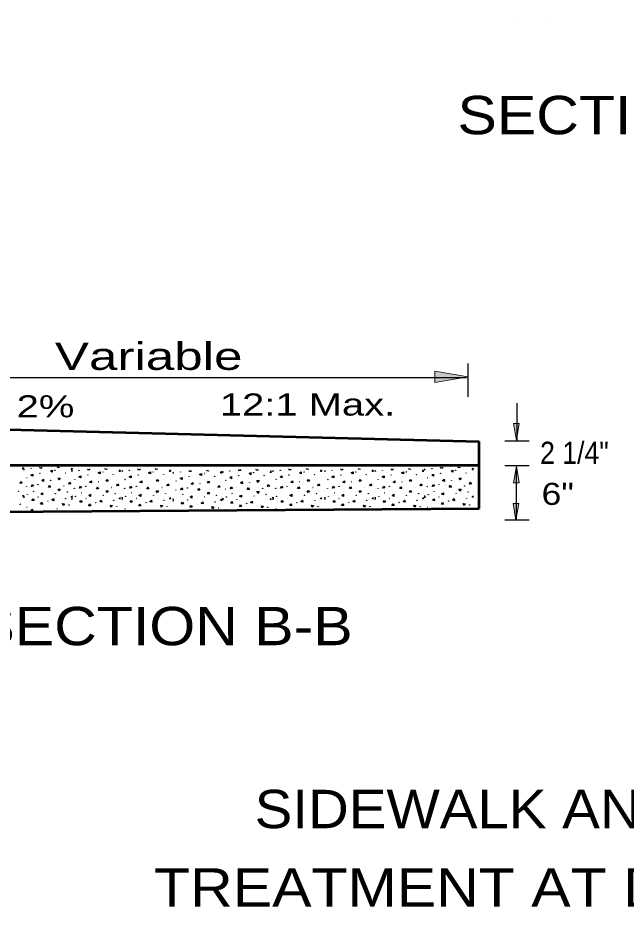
# Model space of a CAD drawing. Extents: x 75.6 to 110.9, y 28 to 50.
# Drawn here: x 94.747 to 98.089, y 33.984 to 38.874 of the extents above; entities that cross this region are included whole.
import ezdxf
from ezdxf.enums import TextEntityAlignment as Align

# ---------------------------------------------------------------- set-up
doc = ezdxf.new("R2010")
doc.units = 0
doc.header["$LTSCALE"] = 0.06
for name, color, linetype, lineweight in [('1', 7, 'Continuous', 25), ('3', 7, 'Continuous', 13), ('4', 7, 'Continuous', 53)]:
    doc.layers.add(name, color=color, linetype=linetype, lineweight=lineweight)

msp = doc.modelspace()

# ---------------------------------------------------------------- hatches: boundary and pattern name
at = {"layer": '3'}
for points in [[(97.03675, 36.9305), (97.03675, 36.86892), (97.22133, 36.89975), (97.22133, 36.89975)], [(97.50075, 36.644), (97.47, 36.644), (97.48542, 36.55167), (97.48542, 36.55167)], [(97.50075, 36.31617), (97.47, 36.31617), (97.48542, 36.4085), (97.48542, 36.4085)], [(97.49858, 36.20383), (97.46775, 36.20383), (97.48317, 36.1115), (97.48317, 36.1115)]]:
    msp.add_hatch(color=256, dxfattribs=at).paths.add_polyline_path(points)

# ---------------------------------------------------------------- linework, layer by layer
at = {"layer": '1', "lineweight": 53}
for p, q in [((97.28183, 36.17567), (97.28183, 36.54392)), ((93.93933, 36.41383), (97.27217, 36.41383)), ((93.94317, 36.15208), (97.28183, 36.17567))]:
    msp.add_line(p, q, dxfattribs=at)
at = {"layer": '1'}
for p, q in [((94.77275, 36.39208), (94.77858, 36.40208)), ((94.7805, 36.39208), (94.77275, 36.39208)), ((94.778, 36.3945), (94.782, 36.38767)), ((94.782, 36.38767), (94.778, 36.38767)), ((94.77858, 36.40208), (94.7805, 36.39883)), ((94.86742, 36.3975), (94.87075, 36.40325)), ((94.87908, 36.3975), (94.86742, 36.3975)), ((94.87575, 36.40325), (94.87908, 36.3975)), ((94.96258, 36.40267), (94.96333, 36.40325)), ((94.97358, 36.39867), (94.96258, 36.40267)), ((94.97275, 36.40325), (94.97358, 36.39867)), ((95.04033, 36.38767), (95.04608, 36.39767)), ((95.048, 36.38767), (95.04033, 36.38767)), ((95.04117, 36.38567), (95.04508, 36.37883)), ((95.04608, 36.39767), (95.048, 36.3945)), ((95.13058, 36.38867), (95.134, 36.3945)), ((95.14225, 36.38867), (95.13058, 36.38867)), ((95.13892, 36.3945), (95.14225, 36.38867)), ((95.22575, 36.39383), (95.22642, 36.3945)), ((95.23667, 36.38983), (95.22575, 36.39383)), ((95.23592, 36.3945), (95.23667, 36.38983)), ((95.30342, 36.37883), (95.30925, 36.38883)), ((95.30925, 36.38883), (95.31117, 36.38567)), ((95.31733, 36.38567), (95.32133, 36.37883)), ((95.40683, 36.38867), (95.41017, 36.3945)), ((95.4185, 36.38867), (95.40683, 36.38867)), ((95.41517, 36.3945), (95.4185, 36.38867)), ((95.502, 36.39383), (95.50267, 36.3945)), ((95.513, 36.38983), (95.502, 36.39383)), ((95.51217, 36.3945), (95.513, 36.38983)), ((95.57967, 36.37883), (95.5855, 36.38883)), ((95.5855, 36.38883), (95.58733, 36.38567)), ((95.68758, 36.37992), (95.69092, 36.38567)), ((95.69917, 36.37992), (95.68758, 36.37992)), ((95.69583, 36.38567), (95.69917, 36.37992)), ((95.78267, 36.38517), (95.78333, 36.38567)), ((95.79367, 36.38117), (95.78267, 36.38517)), ((95.79283, 36.38567), (95.79367, 36.38117)), ((95.86033, 36.37008), (95.86617, 36.38017)), ((95.86617, 36.38017), (95.86808, 36.37683)), ((95.87, 36.38125), (95.874, 36.3745)), ((95.95942, 36.38433), (95.96275, 36.39008)), ((95.97108, 36.38433), (95.95942, 36.38433)), ((95.96775, 36.39008), (95.97108, 36.38433)), ((96.05458, 36.3895), (96.05533, 36.39008)), ((96.06558, 36.3855), (96.05458, 36.3895)), ((96.06475, 36.39008), (96.06558, 36.3855)), ((96.13233, 36.3745), (96.13808, 36.3845)), ((96.13808, 36.3845), (96.14, 36.38125)), ((96.14633, 36.38567), (96.15025, 36.37883)), ((96.23575, 36.38875), (96.23908, 36.3945)), ((96.24733, 36.38875), (96.23575, 36.38875)), ((96.244, 36.3945), (96.24733, 36.38875)), ((96.33092, 36.39392), (96.33158, 36.3945)), ((96.34183, 36.38992), (96.33092, 36.39392)), ((96.341, 36.3945), (96.34183, 36.38992)), ((96.40858, 36.37883), (96.41433, 36.38892)), ((96.41433, 36.38892), (96.41633, 36.38567)), ((96.43133, 36.38567), (96.43533, 36.37883)), ((96.52075, 36.38875), (96.52417, 36.3945)), ((96.53242, 36.38875), (96.52075, 36.38875)), ((96.52908, 36.3945), (96.53242, 36.38875)), ((96.616, 36.39392), (96.61667, 36.3945)), ((96.62692, 36.38992), (96.616, 36.39392)), ((96.62608, 36.3945), (96.62692, 36.38992)), ((96.69367, 36.37883), (96.69942, 36.38892)), ((96.69942, 36.38892), (96.70133, 36.38567)), ((96.70767, 36.38567), (96.71158, 36.37883)), ((96.79708, 36.38875), (96.80042, 36.3945)), ((96.80875, 36.38875), (96.79708, 36.38875)), ((96.80533, 36.3945), (96.80875, 36.38875)), ((96.89225, 36.39392), (96.893, 36.3945)), ((96.90317, 36.38992), (96.89225, 36.39392)), ((96.90233, 36.3945), (96.90317, 36.38992)), ((96.97, 36.37883), (96.97575, 36.38892)), ((96.97575, 36.38892), (96.97767, 36.38567)), ((96.97958, 36.3945), (96.9835, 36.38767)), ((96.9835, 36.38767), (96.97958, 36.38767)), ((97.069, 36.3975), (97.07233, 36.40325)), ((97.08067, 36.3975), (97.069, 36.3975)), ((97.07733, 36.40325), (97.08067, 36.3975)), ((97.16417, 36.40267), (97.16483, 36.40325)), ((97.17508, 36.39867), (97.16417, 36.40267)), ((97.17433, 36.40325), (97.17508, 36.39867)), ((97.24183, 36.38767), (97.24767, 36.39767)), ((97.24958, 36.38767), (97.24183, 36.38767)), ((97.24767, 36.39767), (97.24958, 36.3945)), ((95.04508, 36.37883), (95.04117, 36.37883)), ((95.31117, 36.37883), (95.30342, 36.37883)), ((95.32133, 36.37883), (95.31733, 36.37883)), ((95.58733, 36.37883), (95.57967, 36.37883)), ((95.59808, 36.37683), (95.602, 36.37008)), ((95.602, 36.37008), (95.59808, 36.37008)), ((95.86808, 36.37008), (95.86033, 36.37008)), ((95.874, 36.3745), (95.87, 36.3745)), ((96.14, 36.3745), (96.13233, 36.3745)), ((96.15025, 36.37883), (96.14633, 36.37883)), ((96.41633, 36.37883), (96.40858, 36.37883)), ((96.43533, 36.37883), (96.43133, 36.37883)), ((96.70133, 36.37883), (96.69367, 36.37883)), ((96.71158, 36.37883), (96.70767, 36.37883)), ((96.97767, 36.37883), (96.97, 36.37883)), ((94.778, 36.24483), (94.78033, 36.24625)), ((94.778, 36.24483), (94.78033, 36.24625)), ((94.78033, 36.23458), (94.778, 36.23592)), ((94.78033, 36.23458), (94.778, 36.23592)), ((94.78033, 36.24625), (94.78033, 36.23458)), ((94.78033, 36.24625), (94.78033, 36.23458)), ((95.04117, 36.23608), (95.04342, 36.2375)), ((95.04117, 36.23608), (95.04342, 36.2375)), ((95.04342, 36.2375), (95.0435, 36.22583)), ((95.04342, 36.2375), (95.0435, 36.22583)), ((95.31733, 36.23608), (95.31967, 36.2375)), ((95.31733, 36.23608), (95.31967, 36.2375)), ((95.31967, 36.2375), (95.31975, 36.22583)), ((95.31967, 36.2375), (95.31975, 36.22583)), ((95.87, 36.23175), (95.87233, 36.23308)), ((95.87, 36.23175), (95.87233, 36.23308)), ((95.87233, 36.23308), (95.87233, 36.2215)), ((95.87233, 36.23308), (95.87233, 36.2215)), ((96.14633, 36.23617), (96.14858, 36.2375)), ((96.14633, 36.23617), (96.14858, 36.2375)), ((96.14858, 36.2375), (96.14867, 36.22583)), ((96.14858, 36.2375), (96.14867, 36.22583)), ((96.43133, 36.23617), (96.43367, 36.2375)), ((96.43133, 36.23617), (96.43367, 36.2375)), ((96.43367, 36.2375), (96.43367, 36.22583)), ((96.43367, 36.2375), (96.43367, 36.22583)), ((96.70767, 36.23617), (96.71, 36.2375)), ((96.70767, 36.23617), (96.71, 36.2375)), ((96.71, 36.2375), (96.71, 36.22583)), ((96.71, 36.2375), (96.71, 36.22583)), ((96.97958, 36.24483), (96.98183, 36.24625)), ((96.97958, 36.24483), (96.98183, 36.24625)), ((96.98192, 36.23458), (96.97958, 36.23592)), ((96.98192, 36.23458), (96.97958, 36.23592)), ((96.98183, 36.24625), (96.98192, 36.23458)), ((96.98183, 36.24625), (96.98192, 36.23458)), ((95.0435, 36.22583), (95.04117, 36.22717)), ((95.0435, 36.22583), (95.04117, 36.22717)), ((95.31975, 36.22583), (95.31733, 36.22717)), ((95.31975, 36.22583), (95.31733, 36.22717)), ((95.59808, 36.22733), (95.60033, 36.22867)), ((95.59808, 36.22733), (95.60033, 36.22867)), ((95.60042, 36.21708), (95.59808, 36.21842)), ((95.60042, 36.21708), (95.59808, 36.21842)), ((95.60033, 36.22867), (95.60042, 36.21708)), ((95.60033, 36.22867), (95.60042, 36.21708)), ((95.87233, 36.2215), (95.87, 36.22283)), ((95.87233, 36.2215), (95.87, 36.22283)), ((96.14867, 36.22583), (96.14633, 36.22717)), ((96.14867, 36.22583), (96.14633, 36.22717)), ((96.43367, 36.22583), (96.43133, 36.22717)), ((96.43367, 36.22583), (96.43133, 36.22717)), ((96.71, 36.22583), (96.70767, 36.22717)), ((96.71, 36.22583), (96.70767, 36.22717))]:
    msp.add_line(p, q, dxfattribs=at)
for points in [[(94.93558, 36.37508), (94.9255, 36.38083), (94.93558, 36.38675)], [(97.13717, 36.37508), (97.127, 36.38083), (97.13708, 36.38675)], [(94.82925, 36.35275), (94.81917, 36.35858), (94.82917, 36.3645)], [(94.88883, 36.325), (94.87833, 36.32983), (94.88775, 36.3365)], [(94.97458, 36.3325), (94.96867, 36.34267), (94.98033, 36.34267)], [(95.09233, 36.34392), (95.08233, 36.34983), (95.09233, 36.35567)], [(95.19875, 36.36625), (95.18867, 36.37208), (95.19867, 36.37792)], [(95.23767, 36.32375), (95.23183, 36.33383), (95.2435, 36.33383)], [(95.36867, 36.34392), (95.35858, 36.34983), (95.36858, 36.35567)], [(95.475, 36.36625), (95.46492, 36.37208), (95.475, 36.37792)], [(95.514, 36.32375), (95.50808, 36.33383), (95.51975, 36.33383)], [(95.64933, 36.33517), (95.63925, 36.34108), (95.64925, 36.34683)], [(95.75567, 36.3575), (95.74558, 36.36333), (95.75567, 36.36917)], [(95.92125, 36.33958), (95.91117, 36.3455), (95.92117, 36.35125)], [(96.02758, 36.36183), (96.0175, 36.36775), (96.02758, 36.37358)], [(96.19758, 36.344), (96.18742, 36.34983), (96.19742, 36.35567)], [(96.30392, 36.36625), (96.29375, 36.37217), (96.30383, 36.378)], [(96.34283, 36.32383), (96.337, 36.33383), (96.34867, 36.33383)], [(96.48258, 36.344), (96.4725, 36.34983), (96.4825, 36.35567)], [(96.589, 36.36625), (96.57883, 36.37217), (96.58892, 36.378)], [(96.62792, 36.32383), (96.622, 36.33383), (96.63367, 36.33383)], [(96.75892, 36.344), (96.74875, 36.34983), (96.75875, 36.35567)], [(96.86525, 36.36625), (96.85517, 36.37217), (96.86517, 36.378)], [(96.90417, 36.32383), (96.89833, 36.33383), (96.91, 36.33383)], [(97.03075, 36.35275), (97.02067, 36.35858), (97.03067, 36.3645)], [(97.09033, 36.325), (97.07983, 36.32983), (97.08933, 36.3365)], [(97.17608, 36.3325), (97.17025, 36.34267), (97.18192, 36.34267)], [(94.77075, 36.31617), (94.75933, 36.31417), (94.76333, 36.32508)], [(94.83367, 36.29833), (94.82225, 36.29633), (94.82617, 36.30725)], [(94.92717, 36.29367), (94.9155, 36.29367), (94.92133, 36.30375)], [(94.97408, 36.27167), (94.96825, 36.28183), (94.97992, 36.28183)], [(95.03833, 36.31175), (95.02683, 36.30975), (95.03075, 36.32067)], [(95.09683, 36.2895), (95.08533, 36.2875), (95.08933, 36.2985)], [(95.152, 36.31617), (95.14142, 36.32108), (95.151, 36.32775)], [(95.19033, 36.28483), (95.17867, 36.28483), (95.18442, 36.29492)], [(95.30142, 36.30292), (95.29, 36.30092), (95.294, 36.31183)], [(95.37308, 36.2895), (95.36167, 36.2875), (95.36558, 36.2985)], [(95.42825, 36.31617), (95.41767, 36.32108), (95.42717, 36.32775)], [(95.46658, 36.28483), (95.45492, 36.28483), (95.46067, 36.29492)], [(95.57767, 36.30292), (95.56625, 36.30092), (95.57017, 36.31183)], [(95.65375, 36.28083), (95.64233, 36.27883), (95.64633, 36.28975)], [(95.709, 36.3075), (95.69833, 36.31233), (95.70792, 36.319)], [(95.74725, 36.27617), (95.73558, 36.27617), (95.74133, 36.28617)], [(95.79467, 36.315), (95.78875, 36.32508), (95.80042, 36.32508)], [(95.85833, 36.29417), (95.847, 36.29217), (95.85092, 36.30308)], [(95.92567, 36.28517), (95.91425, 36.28317), (95.91817, 36.29417)], [(95.98083, 36.31183), (95.97033, 36.31675), (95.97975, 36.32342)], [(96.01917, 36.2805), (96.0075, 36.2805), (96.01333, 36.29058)], [(96.06658, 36.31942), (96.06067, 36.3295), (96.07233, 36.3295)], [(96.13033, 36.29858), (96.11883, 36.29658), (96.12275, 36.3075)], [(96.202, 36.28958), (96.19058, 36.28758), (96.1945, 36.2985)], [(96.25717, 36.31625), (96.24658, 36.32117), (96.25608, 36.32783)], [(96.29542, 36.28492), (96.28375, 36.28492), (96.28958, 36.295)], [(96.40658, 36.303), (96.39517, 36.301), (96.39908, 36.31183)], [(96.487, 36.28958), (96.47558, 36.28758), (96.47958, 36.2985)], [(96.54217, 36.31625), (96.53167, 36.32117), (96.54117, 36.32783)], [(96.5805, 36.28492), (96.56883, 36.28492), (96.57467, 36.295)], [(96.69167, 36.303), (96.68017, 36.301), (96.68417, 36.31183)], [(96.76333, 36.28958), (96.75192, 36.28758), (96.75583, 36.2985)], [(96.8185, 36.31625), (96.808, 36.32117), (96.81742, 36.32783)], [(96.85675, 36.28492), (96.84517, 36.28492), (96.851, 36.295)], [(96.968, 36.303), (96.9565, 36.301), (96.96042, 36.31183)], [(97.03525, 36.29833), (97.02375, 36.29633), (97.02775, 36.30725)], [(97.12867, 36.29367), (97.117, 36.29367), (97.12283, 36.30375)], [(97.17567, 36.27167), (97.16975, 36.28183), (97.18142, 36.28183)], [(97.23983, 36.31175), (97.22833, 36.30975), (97.23233, 36.32067)], [(94.88317, 36.25117), (94.87308, 36.257), (94.88317, 36.26283)], [(95.14633, 36.24233), (95.13625, 36.24817), (95.14633, 36.254)], [(95.23725, 36.26283), (95.23133, 36.273), (95.243, 36.273)], [(95.42258, 36.24233), (95.4125, 36.24817), (95.42258, 36.254)], [(95.5135, 36.26283), (95.50767, 36.273), (95.51933, 36.273)], [(95.70333, 36.23358), (95.69317, 36.2395), (95.70325, 36.24525)], [(95.79417, 36.25417), (95.78833, 36.26425), (95.8, 36.26425)], [(95.97517, 36.238), (95.96508, 36.24383), (95.97517, 36.24967)], [(96.06608, 36.2585), (96.06025, 36.26867), (96.07192, 36.26867)], [(96.2515, 36.24242), (96.24133, 36.24825), (96.25142, 36.25408)], [(96.34233, 36.26292), (96.33658, 36.27308), (96.34817, 36.27308)], [(96.53658, 36.24242), (96.52642, 36.24825), (96.5365, 36.25408)], [(96.62742, 36.26292), (96.62158, 36.27308), (96.63325, 36.27308)], [(96.81283, 36.24242), (96.80275, 36.24825), (96.81275, 36.25408)], [(96.90375, 36.26292), (96.89792, 36.27308), (96.90958, 36.27308)], [(97.08475, 36.25117), (97.07467, 36.257), (97.08467, 36.26283)], [(94.83642, 36.21908), (94.82475, 36.21908), (94.83058, 36.22917)], [(94.884, 36.20017), (94.87233, 36.20017), (94.87808, 36.21025)], [(94.94433, 36.21883), (94.93333, 36.22283), (94.94233, 36.23025)], [(94.9955, 36.1925), (94.9925, 36.20367), (95.00375, 36.20067)], [(95.09958, 36.21025), (95.088, 36.21025), (95.09375, 36.22033)], [(95.14708, 36.19142), (95.13542, 36.19142), (95.14125, 36.2015)], [(95.2075, 36.21), (95.19658, 36.214), (95.20542, 36.2215)], [(95.25867, 36.18367), (95.25567, 36.19483), (95.26692, 36.19183)], [(95.37583, 36.21025), (95.36417, 36.21025), (95.37, 36.22033)], [(95.42333, 36.19142), (95.41167, 36.19142), (95.4175, 36.2015)], [(95.48375, 36.21), (95.47275, 36.214), (95.48167, 36.2215)], [(95.53492, 36.18367), (95.53192, 36.19483), (95.54317, 36.19183)], [(95.65658, 36.2015), (95.64492, 36.2015), (95.65067, 36.21158)], [(95.704, 36.18267), (95.69233, 36.18267), (95.69817, 36.19267)], [(95.76442, 36.20125), (95.7535, 36.20525), (95.76233, 36.21267)], [(95.81558, 36.17483), (95.81258, 36.18617), (95.82383, 36.18317)], [(95.92842, 36.20592), (95.91675, 36.20592), (95.92258, 36.216)], [(95.976, 36.18708), (95.96433, 36.18708), (95.97008, 36.19708)], [(96.03633, 36.20567), (96.02533, 36.20967), (96.03433, 36.21708)], [(96.0875, 36.17925), (96.0845, 36.1905), (96.09575, 36.1875)], [(96.20475, 36.21033), (96.19308, 36.21033), (96.19892, 36.22042)], [(96.25225, 36.1915), (96.24058, 36.1915), (96.24633, 36.2015)], [(96.31267, 36.21008), (96.30167, 36.21408), (96.31058, 36.2215)], [(96.36375, 36.18367), (96.36075, 36.19492), (96.372, 36.19192)], [(96.48975, 36.21033), (96.47817, 36.21033), (96.484, 36.22042)], [(96.53733, 36.1915), (96.52567, 36.1915), (96.53142, 36.2015)], [(96.59767, 36.21008), (96.58675, 36.21408), (96.59567, 36.2215)], [(96.64883, 36.18367), (96.64583, 36.19492), (96.65708, 36.19192)], [(96.76608, 36.21033), (96.75442, 36.21033), (96.76025, 36.22042)], [(96.81358, 36.1915), (96.802, 36.1915), (96.80775, 36.2015)], [(96.874, 36.21008), (96.863, 36.21408), (96.872, 36.2215)], [(96.92517, 36.18367), (96.92217, 36.19492), (96.93333, 36.19192)], [(97.038, 36.21908), (97.02633, 36.21908), (97.03217, 36.22917)], [(97.0855, 36.20017), (97.07383, 36.20017), (97.07967, 36.21025)], [(97.14592, 36.21883), (97.135, 36.22283), (97.14383, 36.23025)], [(97.197, 36.1925), (97.194, 36.20367), (97.20533, 36.20067)]]:
    msp.add_lwpolyline(points, close=True, dxfattribs=at)
for points in [[(94.7805, 36.24033), (94.77275, 36.24483), (94.7805, 36.24925)], [(95.048, 36.23592), (95.04025, 36.2405), (95.048, 36.24483)], [(95.31117, 36.22717), (95.30333, 36.23167), (95.31117, 36.23608)], [(95.58733, 36.22717), (95.57967, 36.23167), (95.58733, 36.23608)], [(96.41633, 36.22717), (96.40858, 36.23167), (96.41633, 36.23617)], [(96.70133, 36.22717), (96.69358, 36.23167), (96.70133, 36.23617)], [(96.97767, 36.22717), (96.96992, 36.23167), (96.97767, 36.23617)], [(97.24958, 36.23592), (97.24175, 36.2405), (97.24958, 36.24483)], [(95.86808, 36.21842), (95.86033, 36.22283), (95.86808, 36.22733)], [(96.14, 36.22283), (96.13225, 36.22725), (96.14, 36.23175)], [(94.818, 36.16625), (94.82808, 36.17208), (94.82817, 36.1605)]]:
    msp.add_lwpolyline(points, dxfattribs=at)
for centre in [(94.82019, 36.39468), (94.95071, 36.38575), (95.08334, 36.38588), (95.35959, 36.38588), (95.91219, 36.38153), (96.18849, 36.38593), (96.47354, 36.38593), (96.74984, 36.38593), (97.02174, 36.39468), (97.15226, 36.38575), (94.79674, 36.34449), (94.86816, 36.36903), (94.92729, 36.3311), (95.00761, 36.37014), (95.05989, 36.33569), (95.13131, 36.36023), (95.21386, 36.37695), (95.27076, 36.36134), (95.33614, 36.33569), (95.40756, 36.36023), (95.49011, 36.37695), (95.54701, 36.36134), (95.64029, 36.37713), (95.68826, 36.35148), (95.77081, 36.3682), (95.82771, 36.35259), (95.88874, 36.33134), (95.96016, 36.35588), (96.04271, 36.3726), (96.09961, 36.35699), (96.16504, 36.33574), (96.23646, 36.36028), (96.31901, 36.377), (96.37591, 36.36139), (96.45009, 36.33574), (96.52151, 36.36028), (96.60406, 36.377), (96.66096, 36.36139), (96.72639, 36.33574), (96.79781, 36.36028), (96.88036, 36.377), (96.93726, 36.36139), (96.99829, 36.34449), (97.06971, 36.36903), (97.12884, 36.3311), (97.20916, 36.37014), (94.79452, 36.29539), (94.8581, 36.30655), (94.99978, 36.29985), (95.05767, 36.28659), (95.12125, 36.29775), (95.19044, 36.3223), (95.26293, 36.29105), (95.33391, 36.28659), (95.3975, 36.29775), (95.46669, 36.3223), (95.53918, 36.29105), (95.61684, 36.32694), (95.6782, 36.289), (95.74739, 36.31355), (95.81988, 36.2823), (95.88652, 36.28224), (95.9501, 36.2934), (96.01929, 36.31795), (96.09178, 36.2867), (96.16281, 36.28664), (96.2264, 36.2978), (96.29559, 36.32235), (96.36808, 36.2911), (96.44787, 36.28664), (96.51145, 36.2978), (96.58064, 36.32235), (96.65313, 36.2911), (96.72416, 36.28664), (96.78775, 36.2978), (96.85694, 36.32235), (96.92943, 36.2911), (96.99607, 36.29539), (97.05965, 36.30655), (97.20133, 36.29985), (94.75125, 36.27079), (94.8001, 36.25188), (94.83245, 36.27084), (94.8581, 36.23961), (94.95294, 36.25746), (95.01875, 36.26639), (95.06324, 36.24308), (95.0956, 36.26204), (95.21609, 36.24866), (95.2819, 36.25759), (95.33949, 36.24308), (95.37185, 36.26204), (95.49234, 36.24866), (95.55815, 36.25759), (95.61462, 36.27784), (95.6202, 36.23433), (95.65255, 36.25329), (95.77304, 36.23991), (95.83885, 36.24884), (95.8921, 36.23873), (95.92445, 36.25769), (96.04494, 36.24431), (96.11075, 36.25324), (96.16839, 36.24313), (96.20075, 36.26209), (96.32124, 36.24871), (96.38705, 36.25764), (96.45345, 36.24313), (96.4858, 36.26209), (96.60629, 36.24871), (96.6721, 36.25764), (96.72974, 36.24313), (96.7621, 36.26209), (96.88259, 36.24871), (96.9484, 36.25764), (97.00164, 36.25188), (97.034, 36.27084), (97.05965, 36.23961), (97.15449, 36.25746), (97.2203, 36.26639), (94.76018, 36.1994), (94.91165, 36.21729), (95.00984, 36.22958), (95.02768, 36.195), (95.12125, 36.23081), (95.1748, 36.20849), (95.27299, 36.22078), (95.29083, 36.1862), (95.3975, 36.23081), (95.45105, 36.20849), (95.54924, 36.22078), (95.56708, 36.1862), (95.6782, 36.22206), (95.73175, 36.19974), (95.82994, 36.21203), (95.9501, 36.22646), (96.00365, 36.20414), (96.10184, 36.21643), (96.2264, 36.23086), (96.27995, 36.20854), (96.37814, 36.22083), (96.39598, 36.18625), (96.51145, 36.23086), (96.565, 36.20854), (96.66319, 36.22083), (96.68103, 36.18625), (96.78775, 36.23086), (96.8413, 36.20854), (96.93949, 36.22083), (96.95733, 36.18625), (97.1132, 36.21729), (97.21139, 36.22958), (97.22923, 36.195), (94.79674, 36.18161), (94.96187, 36.17378), (95.33614, 36.17281), (95.61684, 36.16406), (95.84778, 36.17745), (95.88874, 36.16846), (96.11968, 36.18185), (96.16504, 36.17286), (96.45009, 36.17286), (96.72639, 36.17286), (96.99829, 36.18161)]:
    msp.add_circle(centre, 0.000647, dxfattribs=at)
at = {"layer": '3'}
for p, q in [((97.49892, 38.87358), (97.49883, 38.87358)), ((97.64375, 38.87358), (97.64367, 38.87358))]:
    msp.add_line(p, q, dxfattribs=at)
at = {"layer": '3', "lineweight": 25}
for p, q in [((97.22017, 36.79025), (97.22017, 36.97308)), ((93.64225, 36.89625), (97.21167, 36.89625)), ((97.48783, 36.75517), (97.48783, 36.54967)), ((97.55533, 36.54625), (97.42233, 36.54625)), ((97.55533, 36.41058), (97.42233, 36.41058)), ((97.48567, 36.11408), (97.48567, 36.40367)), ((97.55533, 36.11158), (97.42233, 36.11158))]:
    msp.add_line(p, q, dxfattribs=at)
at = {"layer": '3'}
for points in [[(97.03675, 36.9305), (97.03675, 36.86892), (97.22133, 36.89975), (97.22133, 36.89975)], [(97.50075, 36.644), (97.47, 36.644), (97.48542, 36.55167), (97.48542, 36.55167)], [(97.50075, 36.31617), (97.47, 36.31617), (97.48542, 36.4085), (97.48542, 36.4085)], [(97.49858, 36.20383), (97.46775, 36.20383), (97.48317, 36.1115), (97.48317, 36.1115)]]:
    msp.add_lwpolyline(points, close=True, dxfattribs=at)
at = {"layer": '4'}
msp.add_line((93.96458, 36.62883), (97.28183, 36.54392), dxfattribs=at)

# ---------------------------------------------------------------- texts
at = {"layer": '1'}
for s, height, width, p in [('SECTION A-A', 0.2109, 1.15, (98.198, 38.23342)), ('Variable', 0.15, 1.4, (95.46579, 36.93783)), ('2% ', 0.1215, 1.35, (94.92933, 36.67683)), ('12:1 Max.', 0.1215, 1.35, (96.33833, 36.68683)), ('2 1/4"', 0.1215, 0.9, (97.80417, 36.42142)), ('6"', 0.1215, 1.2, (97.71258, 36.19567)), ('SECTION B-B', 0.2109, 1.15, (95.55012, 35.42417)), ('SIDEWALK AND CURB', 0.2109, 1.1, (97.70254, 34.41842)), ('TREATMENT AT DRIVEWAYS', 0.2109, 1.15, (97.7565, 33.98692))]:
    msp.add_text(s, height=height, dxfattribs=dict(at, width=width)).set_placement(p, align=Align.CENTER)

doc.saveas('drawing.dxf')
